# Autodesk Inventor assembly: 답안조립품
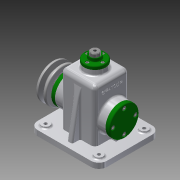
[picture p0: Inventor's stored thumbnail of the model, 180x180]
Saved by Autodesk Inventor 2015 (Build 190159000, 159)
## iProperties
Created: 2016-02
Part Number: 답안조립품
Document SubType Name: Assembly
Designer: Administrator
Author: Administrator
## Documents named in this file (19)
- C:\Users\Administrator\Desktop\460219V1012\답안조립품.iam
- C:\Users\Administrator\Desktop\460219V1012\V-벨트풀리.ipt
- C:\Users\Administrator\Desktop\460219V1012\고정핀.ipt
- C:\Users\Administrator\Desktop\460219V1012\뒤커버.ipt
- C:\Users\Administrator\Desktop\460219V1012\링크.ipt
- C:\Users\Administrator\Desktop\460219V1012\멈춤링 6 x 5.ipt
- C:\Users\Administrator\Desktop\460219V1012\멈춤링 15 x 1.ipt
- C:\Users\Administrator\Desktop\460219V1012\베어링 15 x 35 x 11.ipt
- C:\Users\Administrator\Desktop\460219V1012\본체.ipt
- C:\Users\Administrator\Desktop\460219V1012\볼트 M3 x 8.ipt
- C:\Users\Administrator\Desktop\460219V1012\볼트 M4 x 10.ipt
- C:\Users\Administrator\Desktop\460219V1012\볼트 M6 x 12.ipt
- C:\Users\Administrator\Desktop\460219V1012\상부부시.ipt
- C:\Users\Administrator\Desktop\460219V1012\슬라이드바.ipt
- C:\Users\Administrator\Desktop\460219V1012\앞커버.ipt
- C:\Users\Administrator\Desktop\460219V1012\오일실 15 25 7.ipt
- C:\Users\Administrator\Desktop\460219V1012\와셔.ipt
- C:\Users\Administrator\Desktop\460219V1012\키 5 x 5 x 14.ipt
- C:\Users\Administrator\Desktop\460219V1012\편심축.ipt
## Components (15 placed, 5 different names)
1. V-벨트풀리:1
2. 고정핀:1
3. ISO 4018 M6 x 12:1
4. ISO 4762 M4 x 10:1
5. ISO 4762 M4 x 10:2
6. ISO 4762 M4 x 10:3
7. ISO 4762 M4 x 10:4
8. ISO 4762 M3 x 8:1
9. ISO 4762 M3 x 8:2
10. ISO 4762 M3 x 8:3
11. ISO 4762 M3 x 8:4
12. ISO 4762 M4 x 10:5
13. ISO 4762 M4 x 10:6
14. ISO 4762 M4 x 10:7
15. ISO 4762 M4 x 10:8
